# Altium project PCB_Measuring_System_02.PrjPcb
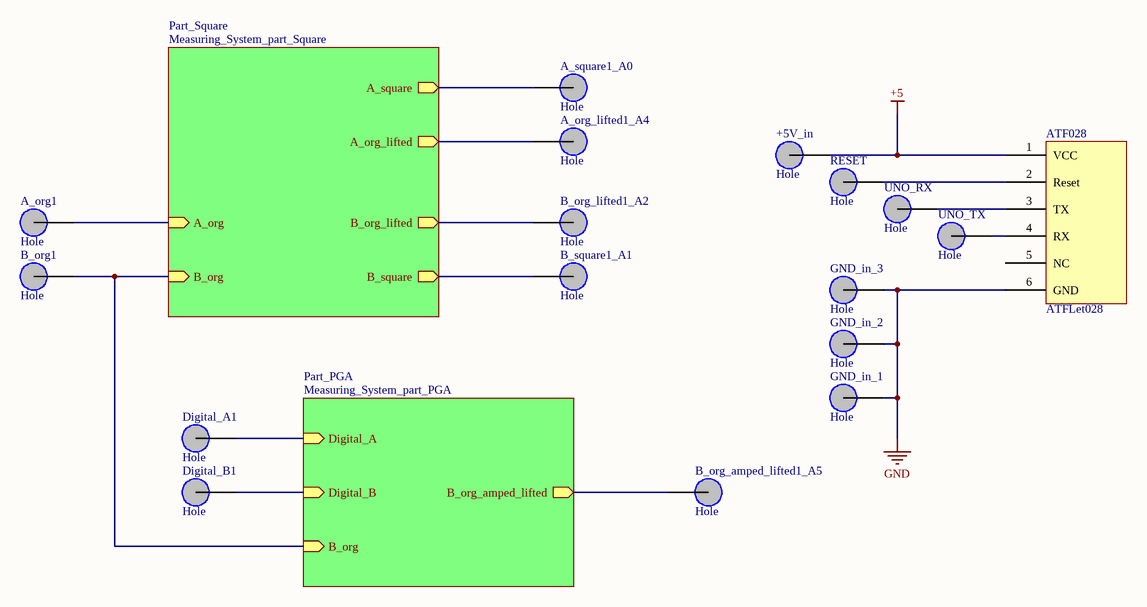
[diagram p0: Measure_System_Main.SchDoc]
3 sheets, 50 parts. Net scope: hierarchical (ports join the sheet entries above them; power ports are global).
Board files: Measure_System_PCB_01.PcbDoc, Measure_System_PCB_02.PcbDoc, Measure_System_PCB_03.PcbDoc, Measure_System_PCB_04.PcbDoc, Measure_System_PCB_05.PcbDoc, Measure_System_PCB_07.PcbDoc, test.PcbDoc, Measure_System_PCB_09.PcbDoc, Measure_System_PCB_10.PcbDoc, Measure_System_PCB_Final.PcbDoc, Measure_System_PCB_Ver2_01.PcbDoc, Measure_System_PCB_Ver2_02.PcbDoc
Sheets:
  Measure_System_Main.SchDoc
    Part_Square = Measuring_System_part_Square.SchDoc
    Part_PGA = Measuring_System_part_PGA.SchDoc

## Sheet Measure_System_Main.SchDoc
size A3

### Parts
+5V_in  Hole  [Hole]
A_org1  Hole  [Hole]
A_org_lifted1_A4  Hole  [Hole]
A_square1_A0  Hole  [Hole]
ATF028  ATFLet028  [ATFLet028]
B_org1  Hole  [Hole]
B_org_amped_lifted1_A5  Hole  [Hole]
B_org_lifted1_A2  Hole  [Hole]
B_square1_A1  Hole  [Hole]
Digital_A1  Hole  [Hole]
Digital_B1  Hole  [Hole]
GND_in_1  Hole  [Hole]
GND_in_2  Hole  [Hole]
GND_in_3  Hole  [Hole]
RESET  Hole  [Hole]
UNO_RX  Hole  [Hole]
UNO_TX  Hole  [Hole]

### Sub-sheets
Part_PGA = Measuring_System_part_PGA: Digital_A (in), Digital_B (in), B_org_amped_lifted (out), B_org (in)
Part_Square = Measuring_System_part_Square: A_square (out), A_org_lifted (out), B_org_lifted (out), B_square (out), A_org (in), B_org (in)

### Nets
+5: +5V_in.1(~PR) ATF028.1(VCC)
GND: ATF028.6(GND) GND_in_1.1(~PR) GND_in_2.1(~PR) GND_in_3.1(~PR)
B_org: B_org1.1(~PR) ; sheet Part_Square/B_org, sheet Part_PGA/B_org
Digital_A: Digital_A1.1(~PR) ; sheet Part_PGA/Digital_A
Digital_B: Digital_B1.1(~PR) ; sheet Part_PGA/Digital_B
NetA_org1_1: A_org1.1(~PR) ; sheet Part_Square/A_org
NetA_org_lifted1_A4_1: A_org_lifted1_A4.1(~PR) ; sheet Part_Square/A_org_lifted
NetA_square1_A0_1: A_square1_A0.1(~PR) ; sheet Part_Square/A_square
NetATF028_2: ATF028.2(Reset) RESET.1(~PR)
NetATF028_3: ATF028.3(TX) UNO_RX.1(~PR)
NetATF028_4: ATF028.4(RX) UNO_TX.1(~PR)
NetB_org_amped_lifted1_A5_1: B_org_amped_lifted1_A5.1(~PR) ; sheet Part_PGA/B_org_amped_lifted
NetB_org_lifted1_A2_1: B_org_lifted1_A2.1(~PR) ; sheet Part_Square/B_org_lifted
NetB_square1_A1_1: B_square1_A1.1(~PR) ; sheet Part_Square/B_square

Not connected (* = marked no-connect by the designer): ATF028 5(NC)

## Sheet Measuring_System_part_Square.SchDoc
size A3
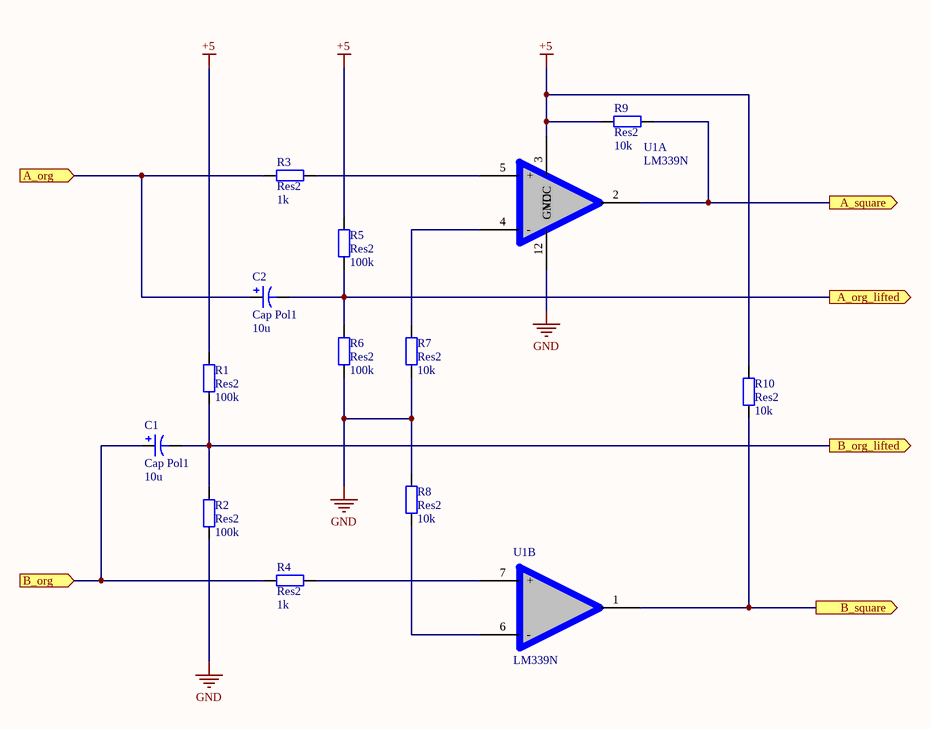
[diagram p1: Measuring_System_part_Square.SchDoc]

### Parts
C1  Cap Pol1  value 10u  [RB5-10.5]
C2  Cap Pol1  value 10u  [RB5-10.5]
R1  Res2  value 100k  [AXIAL-0.4]
R2  Res2  value 100k  [AXIAL-0.4]
R3  Res2  value 1k  [AXIAL-0.4]
R4  Res2  value 1k  [AXIAL-0.4]
R5  Res2  value 100k  [AXIAL-0.4]
R6  Res2  value 100k  [AXIAL-0.4]
R7  Res2  value 10k  [AXIAL-0.4]
R8  Res2  value 10k  [AXIAL-0.4]
R9  Res2  value 10k  [AXIAL-0.4]
R10  Res2  value 10k  [AXIAL-0.4]
U1  LM339N  [LM339N]  (parts A,B of 4)

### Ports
A_org (in), A_org_lifted (out), A_square (out), B_org (in), B_org_lifted (out), B_square (out)

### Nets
+5: R1.2 R5.2 R9.1 R10.2 U1.3(VCC)
GND: R2.1 R6.1 R7.1 R8.2 U1.12(GND)
B_org: C1.1 R4.2 ; port B_org
NetA_org1_1: C2.1 R3.2 ; port A_org
NetA_org_lifted1_A4_1: C2.2 R5.1 R6.2 ; port A_org_lifted
NetA_square1_A0_1: R9.2 U1.2(1OUT) ; port A_square
NetB_org_lifted1_A2_1: C1.2 R1.1 R2.2 ; port B_org_lifted
NetB_square1_A1_1: R10.1 U1.1(2OUT) ; port B_square
NetR3_1: R3.1 U1.5(+)
NetR4_1: R4.1 U1.7(+)
NetR7_2: R7.2 U1.4(-)
NetR8_1: R8.1 U1.6(-)

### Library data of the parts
C1 C2 = Cap Pol1: Polarized Capacitor (Radial)
R1-R10 = Res2: Resistor

## Sheet Measuring_System_part_PGA.SchDoc
size A3
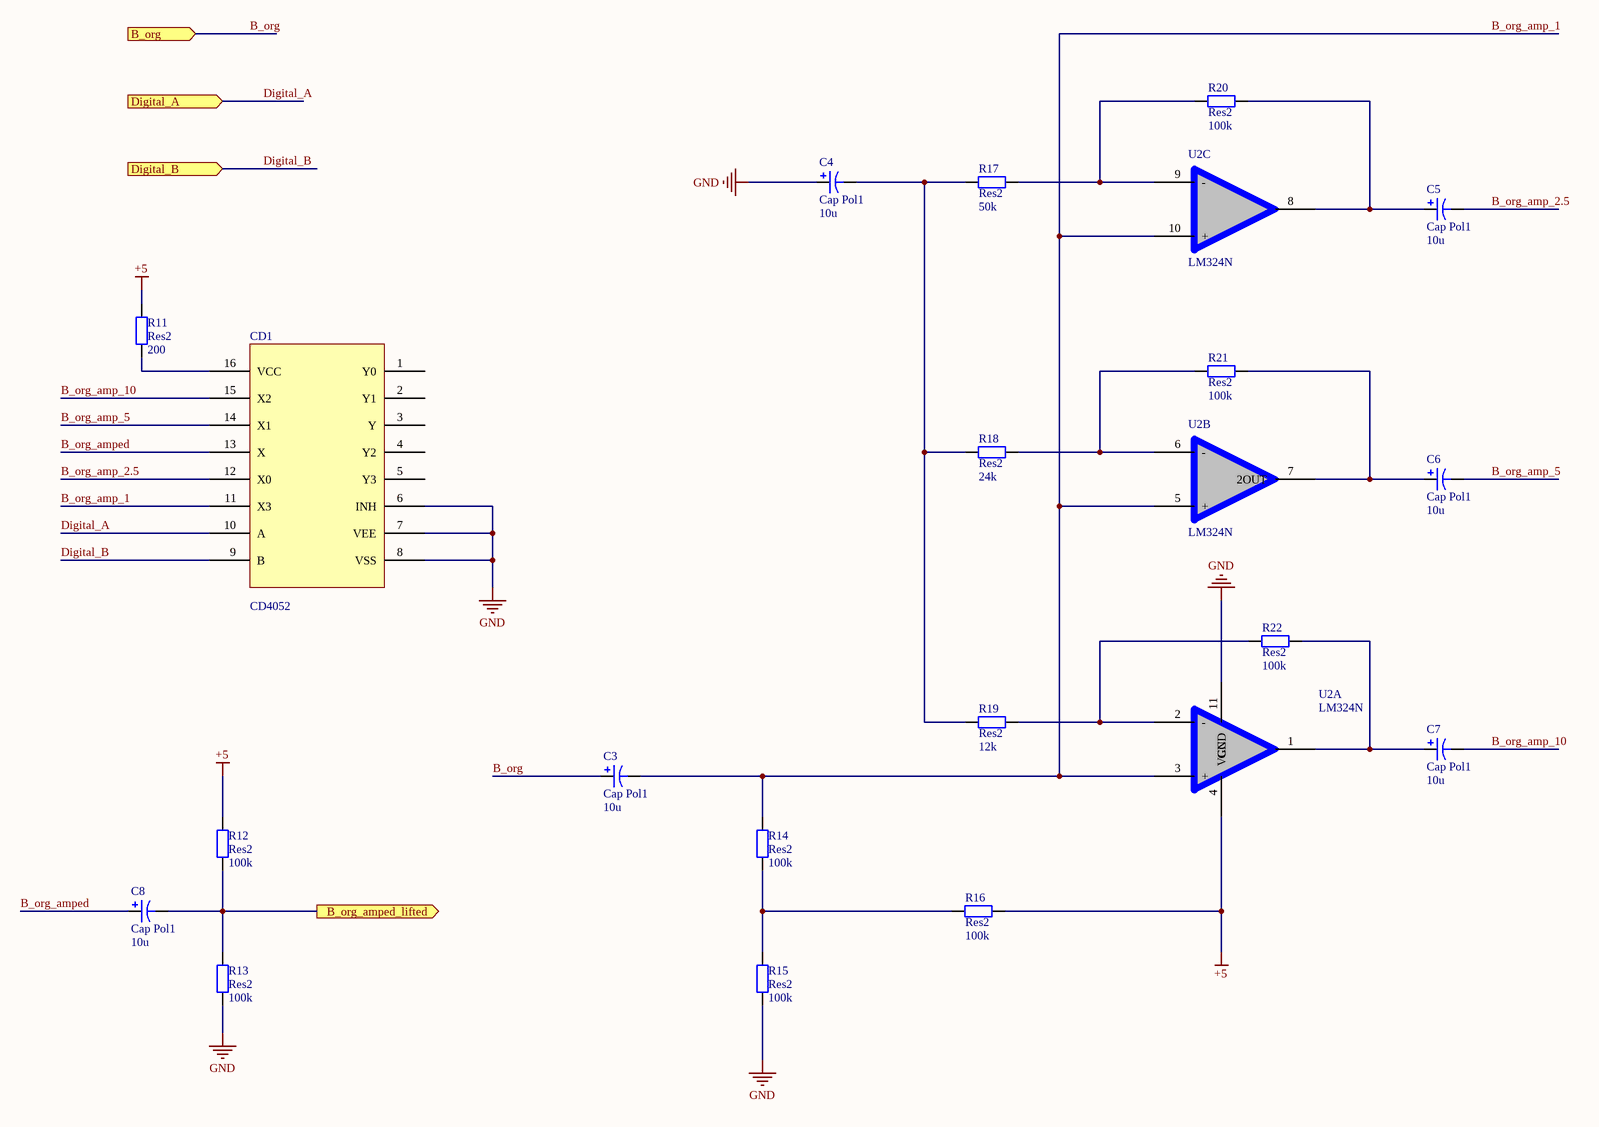
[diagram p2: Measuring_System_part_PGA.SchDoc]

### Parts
C3  Cap Pol1  value 10u  [RB5-10.5]
C4  Cap Pol1  value 10u  [RB5-10.5]
C5  Cap Pol1  value 10u  [RB5-10.5]
C6  Cap Pol1  value 10u  [RB5-10.5]
C7  Cap Pol1  value 10u  [RB5-10.5]
C8  Cap Pol1  value 10u  [RB5-10.5]
CD1  CD4052  [CD4052]
R11  Res2  value 200  [AXIAL-0.4]
R12  Res2  value 100k  [AXIAL-0.4]
R13  Res2  value 100k  [AXIAL-0.4]
R14  Res2  value 100k  [AXIAL-0.4]
R15  Res2  value 100k  [AXIAL-0.4]
R16  Res2  value 100k  [AXIAL-0.4]
R17  Res2  value 50k  [AXIAL-0.4]
R18  Res2  value 24k  [AXIAL-0.4]
R19  Res2  value 12k  [AXIAL-0.4]
R20  Res2  value 100k  [AXIAL-0.4]
R21  Res2  value 100k  [AXIAL-0.4]
R22  Res2  value 100k  [AXIAL-0.4]
U2  LM324N  [LM324N]  (parts A,B,C of 4)

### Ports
B_org (in), B_org_amped_lifted (out), Digital_A (in), Digital_B (in)

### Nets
+5: R11.2 R12.2 R16.1 U2.4(VCC)
GND: C4.1 CD1.6(INH) CD1.7(VEE) CD1.8(VSS) R13.1 R15.1 U2.11(GND)
B_org: C3.1 ; port B_org
B_org_amp_1: C3.2 CD1.11(X3) R14.2 U2.3(+) U2.5(+) U2.10(+)
B_org_amp_2.5: C5.2 CD1.12(X0)
B_org_amp_5: C6.2 CD1.14(X1)
B_org_amp_10: C7.2 CD1.15(X2)
B_org_amped: C8.1 CD1.13(X)
Digital_A: CD1.10(A) ; port Digital_A
Digital_B: CD1.9(B) ; port Digital_B
NetB_org_amped_lifted1_A5_1: C8.2 R12.1 R13.2 ; port B_org_amped_lifted
NetC4_2: C4.2 R17.1 R18.1 R19.1
NetC5_1: C5.1 R20.2 U2.8(3OUT)
NetC6_1: C6.1 R21.2 U2.7(2OUT)
NetC7_1: C7.1 R22.2 U2.1(1OUT)
NetCD1_16: CD1.16(VCC) R11.1
NetR14_1: R14.1 R15.2 R16.2
NetR17_2: R17.2 R20.1 U2.9(-)
NetR18_2: R18.2 R21.1 U2.6(-)
NetR19_2: R19.2 R22.1 U2.2(-)

Not connected (* = marked no-connect by the designer): CD1 1(Y0) 2(Y1) 3(Y) 4(Y2) 5(Y3)

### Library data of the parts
C3-C8 = Cap Pol1: Polarized Capacitor (Radial)
R11-R22 = Res2: Resistor

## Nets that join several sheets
+5: Measure_System_Main (+5V_in.1 ATF028.1), Measuring_System_part_Square (5 pins), Measuring_System_part_PGA (R11.2 R12.2 R16.1 U2.4)
GND: Measure_System_Main (ATF028.6 GND_in_1.1 GND_in_2.1 GND_in_3.1), Measuring_System_part_Square (5 pins), Measuring_System_part_PGA (7 pins)
B_org: Measure_System_Main (B_org1.1), Measuring_System_part_Square (C1.1 R4.2), Measuring_System_part_PGA (C3.1)
Digital_A: Measure_System_Main (Digital_A1.1), Measuring_System_part_PGA (CD1.10)
Digital_B: Measure_System_Main (Digital_B1.1), Measuring_System_part_PGA (CD1.9)
NetA_org1_1: Measure_System_Main (A_org1.1), Measuring_System_part_Square (C2.1 R3.2)
NetA_org_lifted1_A4_1: Measure_System_Main (A_org_lifted1_A4.1), Measuring_System_part_Square (C2.2 R5.1 R6.2)
NetA_square1_A0_1: Measure_System_Main (A_square1_A0.1), Measuring_System_part_Square (R9.2 U1.2)
NetB_org_amped_lifted1_A5_1: Measure_System_Main (B_org_amped_lifted1_A5.1), Measuring_System_part_PGA (C8.2 R12.1 R13.2)
NetB_org_lifted1_A2_1: Measure_System_Main (B_org_lifted1_A2.1), Measuring_System_part_Square (C1.2 R1.1 R2.2)
NetB_square1_A1_1: Measure_System_Main (B_square1_A1.1), Measuring_System_part_Square (R10.1 U1.1)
